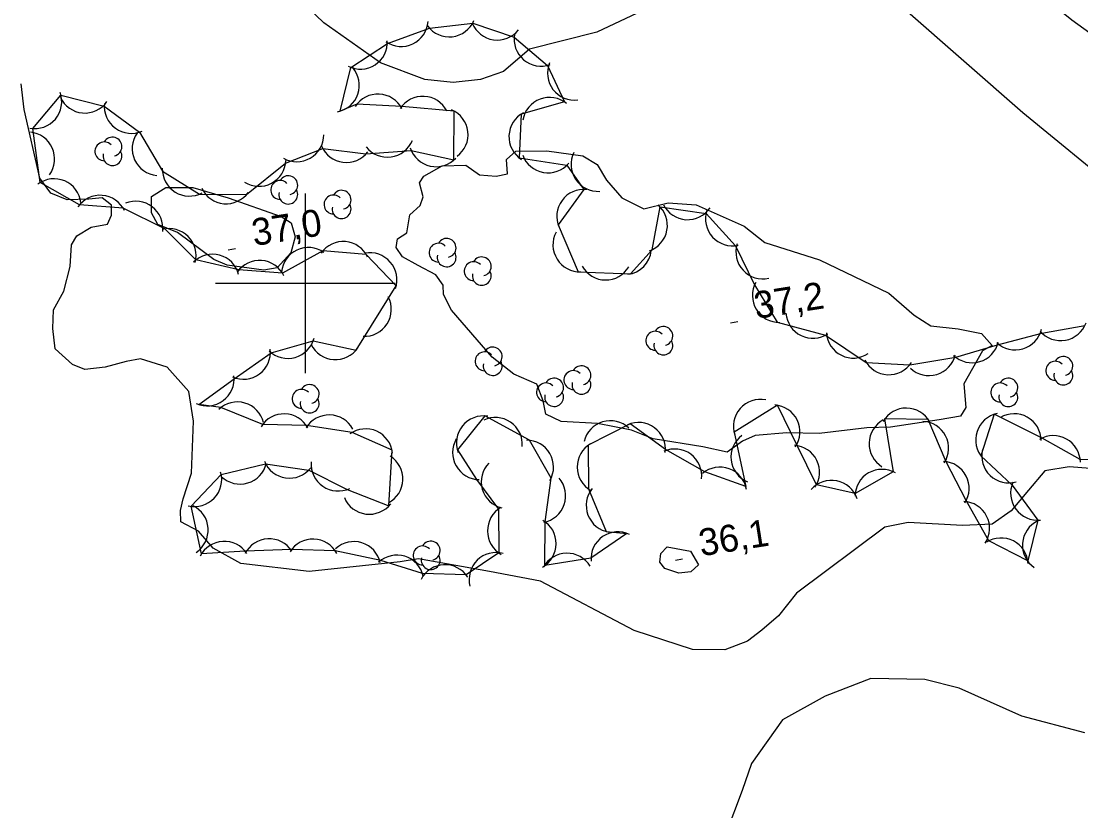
# Model space of a CAD drawing. Extents: x 646142 to 649934, y 5874075 to 5876351.
# Drawn here: x 648768.4 to 648886.2, y 5875141.4 to 5875229.1 of the extents above; entities that cross this region are included whole.
import ezdxf

# ---------------------------------------------------------------- set-up
doc = ezdxf.new("R2010")
doc.units = 0
for name, color, linetype in [('Niveau 2', 7, 'Continuous'), ('Niveau 3', 7, 'Continuous'), ('Niveau 44', 7, 'Continuous'), ('Niveau 61', 7, 'Continuous')]:
    doc.layers.add(name, color=color, linetype=linetype)

msp = doc.modelspace()

# ---------------------------------------------------------------- linework, layer by layer
at = {"layer": 'Niveau 2'}
for points in [[(648803.49, 5875295.64), (648811.14, 5875288.25), (648817.91, 5875282.76), (648821.05, 5875281.52), (648826.73, 5875280.51), (648830.1, 5875279.18), (648837.31, 5875276.66), (648844.6, 5875271.93), (648848.16, 5875267.33), (648858.14, 5875254.75), (648870.04, 5875241.52), (648885.23, 5875229.29), (648896.06, 5875221.47)], [(648793.26, 5875272.07), (648793.86, 5875270.98), (648797.9, 5875269.95), (648802.07, 5875267.78), (648804.54, 5875266.45), (648806.55, 5875265.99), (648808.98, 5875266.84), (648812.2, 5875267.78), (648817.74, 5875268.64), (648825.4, 5875268.13), (648830.63, 5875267.69), (648836.25, 5875266.95), (648839.21, 5875265.34), (648844.35, 5875258), (648849.7, 5875250), (648855.21, 5875242.47), (648866.68, 5875230.46), (648879.81, 5875218.98), (648890.67, 5875210.11)], [(648837.54, 5875230.34), (648832.43, 5875227.92), (648824.95, 5875226.04), (648822.04, 5875223.53), (648819.5, 5875222.67), (648816.44, 5875222.32), (648813.29, 5875222.65), (648808.35, 5875224.5), (648802.06, 5875228.94), (648792.57, 5875238.07)], [(648800.42, 5875167.98), (648792.83, 5875168.84), (648789.74, 5875170.56), (648788.13, 5875172.44), (648786.16, 5875173.48), (648786.12, 5875174.75), (648786.42, 5875176.04), (648787.35, 5875178.91), (648787.57, 5875184.68), (648787.06, 5875187.96), (648784.66, 5875190.67), (648781.66, 5875191.6), (648780.09, 5875191.3), (648777.74, 5875190.69), (648775.47, 5875190.43), (648774.13, 5875190.97), (648772.19, 5875192.7), (648771.92, 5875194.97), (648772.02, 5875197.05), (648773.15, 5875199.13), (648773.86, 5875201.86), (648774.02, 5875204.29), (648774.6, 5875205.28), (648776.21, 5875206.26), (648778.01, 5875206.58), (648778.47, 5875207.56), (648778.45, 5875208.7), (648777.43, 5875209.51), (648775.95, 5875209.34), (648773.54, 5875209.29), (648771.72, 5875210.01), (648770.48, 5875211.7), (648768.75, 5875219.32), (648768.41, 5875222.16)], [(648844.2, 5875181.84), (648838.69, 5875182.7), (648836.27, 5875183.69), (648832.5, 5875184.41), (648828.45, 5875184.63), (648826.74, 5875185.47), (648826.45, 5875186.93), (648825.76, 5875188.8), (648823.21, 5875189.89), (648820.8, 5875191.79), (648816.26, 5875197.01), (648815.36, 5875198.75), (648815.35, 5875199.78), (648814.52, 5875200.95), (648812.55, 5875201.98), (648810.82, 5875202.93), (648810.12, 5875204), (648810.24, 5875204.93), (648811.3, 5875205.63), (648811.64, 5875207.62), (648812.78, 5875208.66), (648813.12, 5875209.62), (648812.7, 5875211.18), (648813.19, 5875211.92), (648815.23, 5875213.07), (648817.87, 5875213.14), (648819.38, 5875212.05), (648821.24, 5875211.92), (648822.47, 5875212.18), (648822.39, 5875213.77), (648823.43, 5875214.69), (648826.88, 5875214.74), (648830.86, 5875214.16), (648832.47, 5875213.2), (648833.48, 5875211.48), (648835.21, 5875209.5), (648837.66, 5875208.29), (648840.34, 5875208.93), (648843.47, 5875208.72), (648848.82, 5875206.34), (648851.1, 5875204.54), (648857.2, 5875202.6), (648864.89, 5875198.89), (648867.72, 5875196.46), (648869.58, 5875195.29), (648872.61, 5875194.95), (648875.2, 5875194.44), (648876.4, 5875193.09), (648875.32, 5875192.51), (648873.24, 5875188.83), (648873.44, 5875186.21), (648872.87, 5875185.23), (648870.5, 5875184.84), (648865.09, 5875184), (648862.45, 5875183.93), (648857.13, 5875183.32), (648853.56, 5875183.37), (648850.03, 5875183.08), (648848.61, 5875182.46), (648846.92, 5875181.23), (648844.2, 5875181.84)], [(648789.85, 5875202.66), (648785.8, 5875205.64), (648783.62, 5875206.54), (648782.89, 5875207.83), (648782.9, 5875209.67), (648784.51, 5875210.65), (648787.5, 5875210.65), (648791.44, 5875209.49), (648797.33, 5875207.41), (648798.44, 5875206.73), (648798.86, 5875205.17), (648798.38, 5875203.4), (648796.86, 5875201.73), (648795.4, 5875201.45), (648791.3, 5875202.02), (648789.85, 5875202.66)], [(648889.7, 5875179.22), (648884.94, 5875179.59), (648882.23, 5875179.17), (648880.42, 5875177.01), (648878.51, 5875174.72), (648876.39, 5875173.21), (648873.07, 5875173.06), (648867.04, 5875173.41), (648864.46, 5875172.88), (648854.64, 5875165.55), (648852.64, 5875163.03), (648850.76, 5875161.43), (648849.18, 5875160.22), (648846.65, 5875159.24), (648843.07, 5875159.29), (648836.59, 5875161.42), (648826.14, 5875166.9), (648820.48, 5875167.97), (648812.59, 5875169.37), (648810.55, 5875169.03), (648800.42, 5875167.98)], [(648840.25, 5875170.72), (648842.85, 5875170.21), (648843.72, 5875168.7), (648842.89, 5875167.92), (648841.53, 5875167.77), (648839.98, 5875168.28), (648839.43, 5875169.02), (648839.54, 5875169.95), (648840.25, 5875170.72)], [(648886.69, 5875150.04), (648879.67, 5875151.89), (648872.71, 5875155.01), (648868.91, 5875155.95), (648862.9, 5875156.07), (648857.83, 5875154.11), (648853.07, 5875151.49), (648849.62, 5875146.61), (648848.6, 5875143.61), (648846.76, 5875138.79)]]:
    msp.add_lwpolyline(points, dxfattribs=at)
at = {"layer": 'Niveau 3'}
for p, q in [((648791.44, 5875203.73), (648792.23, 5875203.86)), ((648847.3, 5875195.62), (648848.09, 5875195.74)), ((648841.16, 5875169.24), (648841.95, 5875169.36))]:
    msp.add_line(p, q, dxfattribs=at)
at = {"layer": 'Niveau 44'}
for points in [[(648790.61, 5875186.19), (648788.18, 5875186.52), (648792.09, 5875189.39), (648796.21, 5875192.29), (648800.88, 5875193.61), (648805.65, 5875192.58), (648810.11, 5875199.72), (648806.79, 5875203.2), (648801.95, 5875203.62), (648797.46, 5875201.12), (648792.63, 5875201.5), (648787.83, 5875202.61), (648784.4, 5875206.05), (648779.75, 5875208.36), (648774.91, 5875208.74), (648770.53, 5875211.19), (648769.7, 5875217.21), (648772.83, 5875220.92), (648777.65, 5875219.68), (648781.58, 5875216.82), (648784.11, 5875212.48), (648788.23, 5875209.92), (648793.47, 5875209.86), (648797.81, 5875213.35), (648801.94, 5875214.98), (648806.75, 5875214.38), (648811.79, 5875214.76), (648816.53, 5875213.71), (648816.56, 5875219.14), (648810.73, 5875219.67), (648805.74, 5875219.92), (648803.89, 5875219.15), (648805.06, 5875224.01), (648809.13, 5875226.66), (648813.8, 5875228.37), (648818.62, 5875228.92), (648823.23, 5875227.37), (648826.93, 5875224.23), (648828.81, 5875220.16), (648823.99, 5875218.8), (648823.79, 5875213.95), (648829.08, 5875213.12), (648830.98, 5875210.44), (648828.12, 5875206.52), (648830.34, 5875201.29), (648836.18, 5875201.06), (648838.56, 5875203.74), (648839.46, 5875208.51), (648844.58, 5875207.77), (648847.84, 5875204.18), (648849.95, 5875199.83), (648852.46, 5875195.68), (648857.85, 5875194.24), (648862.38, 5875191.2), (648867.23, 5875190.95), (648872.33, 5875191.78), (648876.98, 5875193.17), (648881.92, 5875194.47), (648886.7, 5875195.32)], [(648886.17, 5875180.42), (648881.94, 5875182.79), (648876.62, 5875185.44), (648875.12, 5875180.83), (648878.59, 5875177.58), (648881.45, 5875173.66), (648880.35, 5875169.16), (648876.02, 5875171.37), (648873.49, 5875175.85), (648871.28, 5875180.17), (648869.28, 5875184.87), (648864.42, 5875184.92), (648865.36, 5875179.06), (648861.15, 5875176.63), (648856.84, 5875177.6), (648854.71, 5875181.96), (648852.52, 5875186.45), (648847.68, 5875183.45), (648848.99, 5875177.4), (648844.42, 5875179.05), (648840.05, 5875181.52), (648836.14, 5875184.39), (648831.45, 5875182), (648831.48, 5875177.15), (648833.46, 5875172.42), (648835.76, 5875172.2), (648831.77, 5875169.44), (648826.64, 5875168.62), (648826.69, 5875173.47), (648827.36, 5875178.35), (648824.92, 5875182.55), (648819.98, 5875185.26), (648816.91, 5875181.5), (648819.04, 5875178.2), (648821.48, 5875174.9), (648821.52, 5875170.04), (648817.88, 5875167.6), (648813.03, 5875167.75), (648808.4, 5875169.2), (648803.33, 5875170.25), (648798.48, 5875170.41), (648793.32, 5875170.22), (648788.47, 5875169.94), (648787.3, 5875175.22), (648790.66, 5875178.73), (648795.59, 5875179.94), (648800.39, 5875179.24), (648804.65, 5875177.08), (648809.29, 5875175.27), (648809.65, 5875181.44), (648805.22, 5875183.42), (648800.12, 5875184.2), (648795.27, 5875184.32), (648790.61, 5875186.19)], [(648891.43, 5875180.34), (648886.17, 5875180.42)]]:
    msp.add_lwpolyline(points, dxfattribs=at)
for centre, radius, start, end in [((648810.67, 5875229.33), 3, 235.4868, 355.4647), ((648816.01, 5875230.4), 3, 216.5066, 336.4845), ((648821.35, 5875230.04), 3, 201.8826, 321.8605), ((648826.22, 5875227.14), 3, 169.6588, 289.6368), ((648806.13, 5875226.81), 3, 243.1097, 3.0877), ((648803.01, 5875222.01), 3, 281.0246, 41.0026), ((648829.93, 5875223.37), 3, 157.4375, 277.4154), ((648769.92, 5875220.2), 3, 259.7829, 19.7608), ((648775.5, 5875221.93), 3, 204.7287, 324.7067), ((648808.08, 5875218.04), 3, 27.194, 147.1719), ((648813.07, 5875217.79), 3, 27.194, 147.1719), ((648827.16, 5875217.66), 3, 50.5495, 170.5274), ((648780.65, 5875219.67), 3, 173.8761, 293.8541), ((648815.1, 5875216.52), 3, 306.9182, 66.8962), ((648825.65, 5875216.3), 3, 117.6697, 237.6476), ((648769.13, 5875213.83), 3, 324.1801, 84.158), ((648783.75, 5875214.98), 3, 144.8676, 264.8456), ((648777.66, 5875214.67), 1.05, 44.1154, 269.804), ((648778.56, 5875215.2), 1.05, 282.2692, 149.7263), ((648799.06, 5875216.52), 3, 240.0798, 0.0577), ((648809.13, 5875217.02), 3, 217.8745, 337.8524), ((648778.56, 5875214.15), 1.05, 166.9369, 29.6212), ((648804.57, 5875216.43), 3, 202.824, 322.8019), ((648814.54, 5875215.96), 3, 197.4549, 317.4328), ((648832.56, 5875213.22), 3, 153.4434, 273.4213), ((648794.84, 5875213.78), 3, 237.9409, 357.9188), ((648827, 5875215.28), 3, 199.967, 319.9449), ((648787.1, 5875212.7), 3, 178.2407, 298.2187), ((648772.06, 5875208.62), 3, 6.7308, 126.7088), ((648797.21, 5875210.38), 1.05, 44.1154, 269.804), ((648798.11, 5875210.91), 1.05, 282.2692, 149.7263), ((648777.19, 5875206.79), 3, 25.5108, 145.4887), ((648791.21, 5875211.84), 3, 204.9191, 324.8971), ((648798.11, 5875209.86), 1.05, 166.9369, 29.6212), ((648803.14, 5875208.76), 1.05, 44.1154, 269.804), ((648804.04, 5875209.29), 1.05, 282.2692, 149.7263), ((648830.97, 5875207.44), 3, 83.8113, 203.7892), ((648781.17, 5875206.13), 3, 352.7652, 112.7431), ((648804.04, 5875208.24), 1.05, 166.9369, 29.6212), ((648837.27, 5875206.45), 3, 289.3409, 49.3188), ((648842.52, 5875210.07), 3, 206.4211, 326.399), ((648847.51, 5875207.16), 3, 162.1927, 282.1707), ((648784.86, 5875203.08), 3, 344.9671, 104.9451), ((648815.72, 5875203.94), 1.05, 282.2692, 149.7263), ((648830.54, 5875204.28), 3, 152.0831, 272.0611), ((648800.34, 5875200.98), 3, 54.9612, 174.9392), ((648804.22, 5875201.65), 3, 25.0809, 145.0588), ((648814.82, 5875203.41), 1.05, 44.1154, 269.804), ((648850.89, 5875203.49), 3, 162.7365, 282.7145), ((648789.69, 5875200.23), 3, 14.8086, 134.7866), ((648794.91, 5875199.55), 3, 25.4837, 145.4617), ((648807.19, 5875200.4), 3, 340.9456, 100.9236), ((648815.72, 5875202.89), 1.05, 166.9369, 29.6212), ((648819.63, 5875201.88), 1.05, 282.2692, 149.7263), ((648835.5, 5875203.98), 3, 277.1781, 353.3906), ((648818.73, 5875201.35), 1.05, 44.1154, 269.804), ((648833.4, 5875203.37), 3, 209.5564, 329.5343), ((648819.63, 5875200.83), 1.05, 166.9369, 29.6212), ((648852.72, 5875198.66), 3, 151.1185, 271.0964), ((648806.57, 5875197.11), 3, 267.2745, 27.2525), ((648856.45, 5875196.89), 3, 183.8869, 303.8649), ((648884, 5875196.63), 3, 220.1984, 340.1763), ((648838.92, 5875193.62), 1.05, 44.1154, 269.804), ((648839.82, 5875194.15), 1.05, 282.2692, 149.7263), ((648860.94, 5875194.69), 3, 183.8869, 303.8649), ((648878.95, 5875195.59), 3, 226.5383, 346.5162), ((648798.07, 5875194.65), 3, 225.7282, 345.7061), ((648803.36, 5875194.51), 3, 205.8837, 325.8616), ((648839.82, 5875193.1), 1.05, 166.9369, 29.6212), ((648874.15, 5875194.17), 3, 226.5383, 346.5162), ((648793.12, 5875192.34), 3, 246.3183, 6.2962), ((648819.94, 5875191.33), 1.05, 44.1154, 269.804), ((648820.84, 5875191.86), 1.05, 282.2692, 149.7263), ((648869.36, 5875192.74), 3, 226.5383, 346.5162), ((648820.84, 5875190.81), 1.05, 166.9369, 29.6212), ((648830.71, 5875189.78), 1.05, 282.2692, 149.7263), ((648864.9, 5875192.84), 3, 207.0884, 327.0663), ((648883.4, 5875190.28), 1.05, 44.1154, 269.804), ((648884.3, 5875190.81), 1.05, 282.2692, 149.7263), ((648789.09, 5875189.38), 3, 246.3183, 6.2962), ((648829.81, 5875189.25), 1.05, 44.1154, 269.804), ((648884.3, 5875189.76), 1.05, 166.9369, 29.6212), ((648800.49, 5875187.69), 1.05, 282.2692, 149.7263), ((648826.77, 5875187.88), 1.05, 44.1154, 269.804), ((648827.67, 5875188.41), 1.05, 282.2692, 149.7263), ((648830.71, 5875188.73), 1.05, 166.9369, 29.6212), ((648877.28, 5875187.87), 1.05, 44.1154, 269.804), ((648878.18, 5875188.4), 1.05, 282.2692, 149.7263), ((648799.59, 5875187.16), 1.05, 44.1154, 269.804), ((648827.67, 5875187.36), 1.05, 166.9369, 29.6212), ((648878.18, 5875187.35), 1.05, 166.9369, 29.6212), ((648792.44, 5875183.81), 3, 13.5964, 133.5744), ((648800.49, 5875186.64), 1.05, 166.9369, 29.6212), ((648850.6, 5875184.09), 3, 78.4932, 198.4712), ((648852, 5875183.49), 3, 326.0574, 86.0353), ((648866.83, 5875183.13), 3, 29.4174, 149.3954), ((648797.65, 5875182.49), 3, 28.5598, 148.5378), ((648802.65, 5875182.37), 3, 28.5598, 148.5378), ((648819.81, 5875182.26), 3, 80.8091, 200.787), ((648821.14, 5875182.09), 3, 355.6402, 115.6181), ((648877.55, 5875182.59), 3, 101.8906, 221.8685), ((648878.83, 5875182.5), 3, 0.8175, 120.7955), ((648806.72, 5875180.82), 3, 5.9076, 125.8856), ((648833.92, 5875181.72), 3, 46.6192, 166.5972), ((648837.05, 5875181.53), 3, 353.7743, 113.7523), ((648865.7, 5875182.17), 3, 118.3354, 238.3133), ((648868.54, 5875181.66), 3, 327.1341, 87.112), ((648819.38, 5875181.18), 3, 149.5095, 269.4875), ((648824.61, 5875179.57), 3, 330.0874, 90.0654), ((648850.34, 5875180.69), 3, 126.93, 246.908), ((648883.19, 5875180.07), 3, 0.8175, 120.7955), ((648833.23, 5875179.58), 3, 120.276, 240.2539), ((648841.09, 5875178.58), 3, 353.7743, 113.7523), ((648854.19, 5875179), 3, 326.0574, 86.0353), ((648878.22, 5875180.82), 3, 166.4141, 286.3921), ((648798.25, 5875181.34), 3, 201.7206, 321.6986), ((648807.85, 5875178.25), 3, 297.7267, 57.7046), ((648870.82, 5875177.21), 3, 327.1341, 87.112), ((648787.71, 5875178.19), 3, 256.1834, 16.1613), ((648792.75, 5875180.68), 3, 226.475, 346.4529), ((648803.65, 5875179.91), 3, 175.5556, 295.5336), ((648822.57, 5875177.94), 3, 135.9769, 255.9548), ((648846.11, 5875176.57), 3, 10.0758, 130.0538), ((648864.14, 5875176.32), 3, 60.0049, 179.9829), ((648825.96, 5875176.38), 3, 280.9467, 40.9247), ((648858.52, 5875175.1), 3, 18.6637, 138.6416), ((648881.44, 5875176.66), 3, 156.0656, 276.0435), ((648834.24, 5875175.31), 3, 140.9537, 260.9316), ((648807.12, 5875177.33), 3, 202.5402, 322.5181), ((648873.1, 5875172.76), 3, 327.1341, 87.112), ((648786.2, 5875172.58), 3, 303.8024, 63.7804), ((648823.26, 5875172.48), 3, 120.384, 240.362), ((648824.9, 5875171.07), 3, 299.4074, 59.3854), ((648882.75, 5875170.88), 3, 115.6092, 235.5871), ((648834.77, 5875169.37), 3, 64.6463, 184.6242), ((648790.99, 5875168.32), 3, 33.224, 153.2019), ((648795.99, 5875168.6), 3, 33.224, 153.2019), ((648800.85, 5875168.57), 3, 28.0679, 148.0459), ((648805.41, 5875168.29), 3, 12.5967, 132.5747), ((648813.05, 5875169.75), 1.05, 44.1154, 269.804), ((648813.95, 5875170.28), 1.05, 282.2692, 149.7263), ((648877.38, 5875168.69), 3, 2.9711, 122.9491), ((648810.19, 5875166.79), 3, 12.5967, 132.5747), ((648813.95, 5875169.23), 1.05, 166.9369, 29.6212), ((648821.22, 5875167.08), 3, 74.6892, 194.6671), ((648829.11, 5875167), 3, 31.2335, 151.2114), ((648815.54, 5875165.72), 3, 32.8921, 152.8701)]:
    msp.add_arc(centre, radius, start, end, dxfattribs=at)
at = {"layer": 'Niveau 61'}
for points in [[(648800, 5875210), (648800, 5875200), (648800, 5875190)], [(648790, 5875200), (648800, 5875200), (648810, 5875200)]]:
    msp.add_lwpolyline(points, dxfattribs=at)

# ---------------------------------------------------------------- texts
at = {"layer": 'Niveau 3'}
for s, p in [('37,0 ', (648794.3, 5875204.14)), ('37,2 ', (648850.15, 5875196.03)), ('36,1 ', (648844.01, 5875169.65))]:
    msp.add_text(s, height=3, rotation=8.9405, dxfattribs=at).set_placement(p)

doc.saveas('drawing.dxf')
